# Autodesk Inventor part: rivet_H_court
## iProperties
Created: 2011-01
Part Number: rivet_H_court
Document SubType Name: Modeling
Designer: eric
Density: 1 g/cm^3
Mass: 0.241325 g
Surface Area: 3.62459 cm^2
Volume: 0.241325 cm^3
Author: eric
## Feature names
1. Base1
